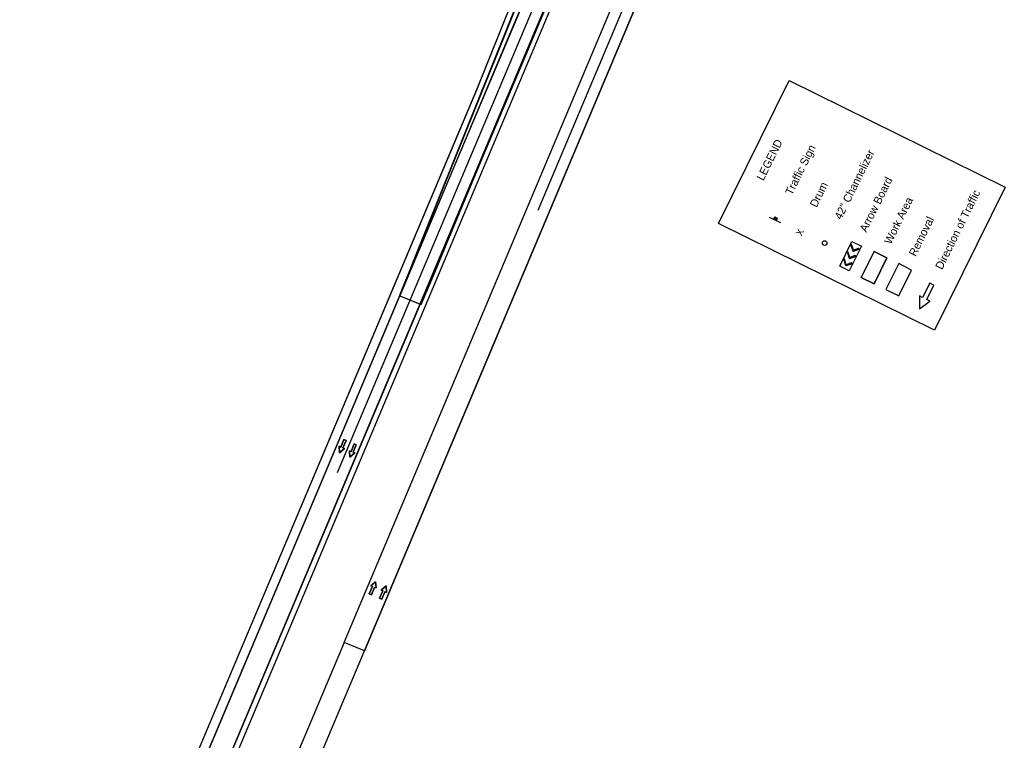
# Model space of a CAD drawing. Extents: x 14090526 to 14125274, y 8637242 to 8677144.
# Drawn here: x 14117998 to 14119075, y 8666958 to 8667745 of the extents above; entities that cross this region are included whole.
import ezdxf

# ---------------------------------------------------------------- set-up
doc = ezdxf.new("R2010")
doc.units = 0
for name, color, linetype in [('dsn_stg_shd_prev', 7, 'Continuous'), ('dsnPaintExistingBrokenLaneLineWhite', 7, 'Continuous'), ('dsnPaintExistingEdgeLineLeftYellow', 7, 'Continuous'), ('dsnPaintExistingEdgeLineRightWhite', 7, 'Continuous'), ('dsnShadingPaved', 7, 'Continuous'), ('dsnStgShadingPropPav', 7, 'Continuous'), ('dsnTextOverlapEven', 7, 'Continuous'), ('Level 2', 7, 'Continuous'), ('Level 5', 7, 'Continuous')]:
    doc.layers.add(name, color=color, linetype=linetype)

msp = doc.modelspace()

# ---------------------------------------------------------------- linework, layer by layer
at = {"layer": 'dsn_stg_shd_prev'}
for p, q in [((14118497.1, 8667669), (14118637.9, 8668019.6)), ((14118497.2, 8667669.3), (14118638, 8668019.9)), ((14118652.6, 8668012.8), (14118415.8, 8667450.6)), ((14118652.6, 8668013.1), (14118415.9, 8667450.9)), ((14118652.6, 8668013.1), (14118415.9, 8667450.9)), ((14115815.8, 8661214.6), (14118674.8, 8668003.7)), ((14115815.8, 8661214.6), (14118674.8, 8668003.7)), ((14118680.7, 8668002), (14115821.7, 8661212.9)), ((14110809.1, 8649412.8), (14118497.1, 8667669)), ((14110809.2, 8649413), (14118497.2, 8667669.3)), ((14118415.8, 8667450.6), (14110817.9, 8649408.4)), ((14118415.9, 8667450.9), (14110818, 8649408.6)), ((14118415.9, 8667450.9), (14110818, 8649408.6))]:
    msp.add_line(p, q, dxfattribs=at)
at = {"layer": 'dsnPaintExistingBrokenLaneLineWhite'}
for p, q in [((14118564.2, 8667537.3), (14118951.7, 8668457.6)), ((14118664.1, 8668009), (14118344.6, 8667250.2))]:
    msp.add_line(p, q, dxfattribs=at)
at = {"layer": 'dsnPaintExistingEdgeLineLeftYellow'}
msp.add_line((14118352.3, 8667065), (14118817.1, 8668168.7), dxfattribs=at)
at = {"layer": 'dsnPaintExistingEdgeLineRightWhite'}
for p, q in [((14118374.4, 8667055.7), (14118962.8, 8668452.9)), ((14118528.4, 8667730.9), (14118413.2, 8667444.3)), ((14118413.2, 8667444.3), (14118306.5, 8667190.7))]:
    msp.add_line(p, q, dxfattribs=at)
msp.add_lwpolyline([(14118682.7, 8668112.5), (14118643.5, 8668017.6), (14118528.4, 8667730.9)], dxfattribs=at)
at = {"layer": 'dsnShadingPaved'}
for p, q in [((14118937.1, 8668391.9), (14118374.4, 8667055.7)), ((14118352.3, 8667065), (14118824.8, 8668187.1)), ((14118413.2, 8667444.3), (14118643.5, 8668017.6)), ((14118576.7, 8667832.4), (14118534.2, 8667731.7)), ((14118534.2, 8667731.7), (14118413, 8667443.7)), ((14116702.8, 8663382.6), (14118413, 8667443.7)), ((14118413, 8667443.7), (14118435.2, 8667434.6)), ((14118435.2, 8667434.6), (14116725, 8663373.3)), ((14118374.4, 8667055.7), (14118352.3, 8667065))]:
    msp.add_line(p, q, dxfattribs=at)
for points in [[(14118576.7, 8667832.4), (14118534.2, 8667731.7), (14118413, 8667443.7), (14118436.3, 8667434.1), (14118452, 8667471.1), (14118467.4, 8667508.1), (14118482.9, 8667545.6), (14118506, 8667600.7), (14118539.1, 8667679.2), (14118556.5, 8667720.5), (14118564.2, 8667738.8), (14118579.8, 8667775.9), (14118598.8, 8667823.1)], [(14118352.3, 8667065), (14117996.2, 8666219.5), (14117609.5, 8665301.3), (14116829, 8663447.7), (14116851.1, 8663438.4), (14116956.9, 8663689.5), (14117040.3, 8663887.7), (14117116, 8664067.4), (14117232.4, 8664343.9), (14117405.1, 8664754), (14117547.8, 8665092.7), (14117686.5, 8665422.2), (14117866, 8665848.4), (14118096, 8666394.5), (14118374.4, 8667055.7)]]:
    msp.add_lwpolyline(points, close=True, dxfattribs=at)
at = {"layer": 'dsnStgShadingPropPav'}
for p, q in [((14118652.6, 8668013.1), (14118415.9, 8667450.9)), ((14115815.8, 8661214.6), (14118674.8, 8668003.7)), ((14118415.9, 8667450.9), (14110818, 8649408.6))]:
    msp.add_line(p, q, dxfattribs=at)
at = {"layer": 'dsnTextOverlapEven'}
for p, q in [((14118816.8, 8667529.7), (14118829.1, 8667523.7)), ((14118821.8, 8667527.7), (14118824.3, 8667526.4)), ((14118824.3, 8667526.3), (14118821.8, 8667527.5)), ((14118824.4, 8667526.5), (14118821.9, 8667527.8)), ((14118822, 8667528.1), (14118824.6, 8667526.8)), ((14118824.5, 8667526.8), (14118822, 8667528)), ((14118822, 8667527.9), (14118824.5, 8667526.7)), ((14118824.6, 8667527), (14118822.1, 8667528.2)), ((14118822.2, 8667528.4), (14118824.7, 8667527.1)), ((14118824.7, 8667527.2), (14118822.2, 8667528.4)), ((14118822.3, 8667528.6), (14118824.8, 8667527.4)), ((14118824.9, 8667527.5), (14118822.4, 8667528.8)), ((14118822.5, 8667529), (14118825, 8667527.7)), ((14118825, 8667527.8), (14118822.5, 8667529)), ((14118822.6, 8667529.2), (14118825.1, 8667528)), ((14118822.7, 8667529.5), (14118825.2, 8667528.2)), ((14118825.2, 8667528.1), (14118822.7, 8667529.3)), ((14118825.3, 8667528.3), (14118822.8, 8667529.6)), ((14118822.9, 8667529.7), (14118825.4, 8667528.5)), ((14118908.7, 8667492.6), (14118914.6, 8667494.6)), ((14118900.9, 8667476.8), (14118906.8, 8667478.8)), ((14118904.8, 8667484.7), (14118910.7, 8667486.7))]:
    msp.add_line(p, q, dxfattribs=at)
for points in [[(14118761.2, 8667522.9), (14118838.4, 8667679.2), (14119074.7, 8667562.4), (14118997.4, 8667406.1)], [(14118761.2, 8667522.9), (14118838.4, 8667679.2), (14119074.7, 8667562.4), (14118997.4, 8667406.1)], [(14118824.2, 8667526.1), (14118821.7, 8667527.4), (14118822.9, 8667529.9), (14118825.5, 8667528.7)], [(14118917.4, 8667498.1), (14118904.1, 8667471.2), (14118893.8, 8667476.3), (14118907.1, 8667503.2)], [(14118945.3, 8667485.2), (14118931.3, 8667492.2), (14118917.3, 8667463.8), (14118931.3, 8667456.9)], [(14118917.3, 8667463.8), (14118931.3, 8667492.2), (14118945.3, 8667485.2), (14118931.3, 8667456.9)], [(14118972.2, 8667471.9), (14118958.2, 8667478.9), (14118944.1, 8667450.5), (14118958.2, 8667443.6)], [(14118972.2, 8667471.9), (14118958.2, 8667478.9), (14118944.1, 8667450.5), (14118958.2, 8667443.6)]]:
    msp.add_lwpolyline(points, close=True, dxfattribs=at)
for points in [[(14118902.1, 8667490.9), (14118902.1, 8667490.9), (14118904.1, 8667485), (14118904.1, 8667485)], [(14118910.4, 8667487.7), (14118910.3, 8667487.7), (14118904.8, 8667485.7), (14118903.1, 8667491.2)], [(14118906, 8667498.9), (14118906, 8667498.8), (14118908, 8667492.9), (14118908, 8667492.9)], [(14118914.3, 8667495.6), (14118914.2, 8667495.6), (14118908.7, 8667493.6), (14118907, 8667499.2)], [(14118898.2, 8667483.1), (14118898.2, 8667483.1), (14118900.2, 8667477.2), (14118900.2, 8667477.2)], [(14118906.5, 8667479.8), (14118906.4, 8667479.8), (14118900.9, 8667477.8), (14118899.2, 8667483.4)], [(14118984.3, 8667442), (14118981, 8667443.6), (14118981, 8667429.6), (14118992.2, 8667438.1), (14118988.8, 8667439.7), (14118996.6, 8667455.4), (14118992.1, 8667457.6), (14118984.3, 8667442)]]:
    msp.add_lwpolyline(points, dxfattribs=at)
msp.add_circle((14118877.3, 8667501.4), 2.5, dxfattribs=at)
msp.add_circle((14118877.3, 8667501.4), 2.5, dxfattribs=at)
for centre, start, end in [((14118902.6, 8667491.1), 16.331, 197.4902), ((14118906.5, 8667499), 16.331, 197.4902), ((14118908.5, 8667493.1), 199.0813, 289.5296), ((14118914.4, 8667495.1), 288.4101, 108.5937), ((14118898.7, 8667483.2), 16.331, 197.4902), ((14118904.6, 8667485.2), 199.0813, 289.5296), ((14118906.6, 8667479.3), 288.4101, 108.5937), ((14118910.5, 8667487.2), 288.4101, 108.5937), ((14118900.7, 8667477.3), 199.0813, 289.5296)]:
    msp.add_arc(centre, 0.515, start, end, dxfattribs=at)
at = {"layer": 'Level 2'}
for points in [[(14118354.3, 8667285.6), (14118352, 8667286.6), (14118348.6, 8667278.5), (14118346.8, 8667279.3), (14118347.3, 8667272.3), (14118352.6, 8667276.9), (14118350.9, 8667277.6)], [(14118365.5, 8667280.9), (14118363.2, 8667281.9), (14118359.8, 8667273.8), (14118358.1, 8667274.5), (14118358.6, 8667267.5), (14118363.9, 8667272.1), (14118362.2, 8667272.8)], [(14118379.7, 8667118.1), (14118382, 8667117.1), (14118385.4, 8667125.2), (14118387.1, 8667124.5), (14118386.7, 8667131.4), (14118381.4, 8667126.9), (14118383.1, 8667126.2)], [(14118391, 8667113.3), (14118393.3, 8667112.4), (14118396.7, 8667120.4), (14118398.5, 8667119.7), (14118398, 8667126.7), (14118392.7, 8667122.1), (14118394.4, 8667121.4)]]:
    msp.add_lwpolyline(points, close=True, dxfattribs=at)
at = {"layer": 'Level 5'}
for points in [[(14118350.9, 8667277.6), (14118352.6, 8667276.9), (14118347.3, 8667272.3), (14118346.8, 8667279.3), (14118348.6, 8667278.5), (14118352, 8667286.6), (14118354.3, 8667285.6), (14118350.9, 8667277.6)], [(14118362.2, 8667272.8), (14118363.9, 8667272.1), (14118358.6, 8667267.5), (14118358.1, 8667274.5), (14118359.8, 8667273.8), (14118363.2, 8667281.9), (14118365.5, 8667280.9), (14118362.2, 8667272.8)], [(14118383.1, 8667126.2), (14118381.4, 8667126.9), (14118386.7, 8667131.4), (14118387.1, 8667124.5), (14118385.4, 8667125.2), (14118382, 8667117.1), (14118379.7, 8667118.1), (14118383.1, 8667126.2)], [(14118394.4, 8667121.4), (14118392.7, 8667122.1), (14118398, 8667126.7), (14118398.5, 8667119.7), (14118396.7, 8667120.4), (14118393.3, 8667112.4), (14118391, 8667113.3), (14118394.4, 8667121.4)]]:
    msp.add_lwpolyline(points, dxfattribs=at)

# ---------------------------------------------------------------- texts
at = {"layer": 'dsnTextOverlapEven'}
for s, height, p in [('LEGEND', 8.75, (14118810.3, 8667568.9)), ('Traffic Sign', 8.75, (14118841.6, 8667553)), ('42" Channelizer ', 8.75, (14118895.4, 8667526.4)), ('Drum', 8.75, (14118868.5, 8667539.7)), ('Arrow Board', 8.75, (14118922.9, 8667512.6)), ('Direction of Traffic', 8.75, (14119005.6, 8667471.7)), ('Work Area', 8.75, (14118949.8, 8667499.3)), ('Removal', 8.75, (14118976.7, 8667486.1)), ('X', 7.5, (14118852.1, 8667508.4))]:
    msp.add_text(s, height=height, rotation=63.6912, dxfattribs=at).set_placement(p)

doc.saveas('drawing.dxf')
